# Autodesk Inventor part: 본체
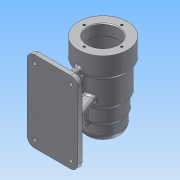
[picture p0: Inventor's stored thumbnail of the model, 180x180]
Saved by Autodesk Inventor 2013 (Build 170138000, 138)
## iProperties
Created: 2016-06
Part Number: 본체
Material: 알루미늄 6061
Document SubType Name: Modeling
Designer: Administrator
Density: 2.71 g/cm^3
Mass: 672.779 g
Surface Area: 647.12 cm^2
Volume: 248.258 cm^3
Author: Administrator
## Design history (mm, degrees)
sketch "스케치1"
  geometry: C1 r 34 at (0, 0); 1 further point
  constraints: 1 centre point, 1 coincident
  dimensions: "d0" = 68 diameter of C1
extrude "돌출1" new body sketch "스케치1" distance "d1" = 28; taper "d2" = 0 deg
sketch "스케치2"
  geometry: C1 r 34 at (0, 0) reference; C2 r 30 at (0, 0)
  constraints: 1 centre point, 1 coincident
  dimensions: "d3" = 60 diameter of C2
extrude "돌출2" join sketch "스케치2" distance "d4" = 39; taper "d5" = 0 deg
sketch "스케치3"
  geometry: C1 r 30 at (0, 0) reference; C2 r 27 at (0, 0)
  constraints: 1 centre point, 1 coincident
  dimensions: "d6" = 54 diameter of C2
extrude "돌출3" join sketch "스케치3" distance "d7" = 20; taper "d8" = 0 deg
sketch "스케치4"
  geometry: C1 r 27 at (0, 0) reference; C2 r 25 at (0, 0)
  constraints: 1 centre point, 1 coincident
  dimensions: "d9" = 50 diameter of C2
extrude "돌출4" join sketch "스케치4" distance "d10" = 25; taper "d11" = 0 deg
hole "구멍1" diameter "d14" = 42; stored, may be unused: countersink angle "d18" = 90 deg, drill point angle "d20" = 0 deg; dims "d12" = 10, "d13" = 10, "d15" = 6, "d16" = 4, "d17" = 2, "d19" = 15
hole "구멍2" diameter "d23" = 48; stored, may be unused: countersink angle "d27" = 90 deg, drill point angle "d29" = 0 deg; dims "d21" = 10, "d22" = 10, "d24" = 6, "d25" = 4, "d26" = 2, "d28" = 54
hole "구멍3" diameter "d32" = 42; stored, may be unused: countersink angle "d36" = 90 deg, drill point angle "d38" = 0 deg; dims "d30" = 10, "d31" = 10, "d33" = 6, "d34" = 4, "d35" = 2, "d37" = 12
hole "구멍4" diameter "d41" = 35; stored, may be unused: countersink angle "d45" = 90 deg, drill point angle "d47" = 0 deg; dims "d39" = 10, "d40" = 10, "d42" = 6, "d43" = 4, "d44" = 2, "d46" = 18
hole "구멍5" diameter "d50" = 32; stored, may be unused: countersink angle "d54" = 90 deg, drill point angle "d56" = 0 deg; dims "d48" = 10, "d49" = 10, "d51" = 6, "d52" = 4, "d53" = 2, "d55" = 4
hole "구멍6" diameter "d59" = 21; stored, may be unused: countersink angle "d63" = 90 deg, drill point angle "d65" = 0 deg; dims "d57" = 10, "d58" = 10, "d60" = 6, "d61" = 4, "d62" = 2, "d64" = 3
node "작업 평면1"
sketch "스케치5"
  geometry: L1 (-25, -112)-(25, -112) reference; L2 (-34, 0)-(34, 0) reference; L3 (27.711, -56)-(106.129, -56); L4 (-35, -112)-(35, -112); L5 (35, -112)-(35, 0); L6 (35, 0)-(-35, 0); L7 (-35, 0)-(-35, -112); L8 (-35, -112)-(35, 0); L9 (35, -112)-(-35, 0); 5 further points
  constraints: 14 end point, 5 midpoint, 2 parallel, 1 horizontal, 1 perpendicular, 1 point on line, 1 vertical alignment
  dimensions: "d69" = 56 distance between parallel lines of L3 L1; "d70" = 70 distance of L6.end L5.end; "d72" = 112 distance between parallel lines of L6 L4
extrude "돌출5" join sketch "스케치5" distance "d73" = 10; taper "d74" = 0 deg
fillet "모깎기7" dims "d133" = 3
sketch "스케치6"
  geometry: L1 (-35, 0)-(35, 0) reference; L2 (35, 0)-(35, 112) reference; L3 (4, 20)-(4, 92); L4 (4, 92)-(-4, 92); L5 (-4, 92)-(-4, 20); L6 (-4, 20)-(4, 20); L7 (4, 56)-(-4, 56); L8 (0, 92)-(0, 20); 1 further point
  constraints: 12 end point, 4 midpoint, 2 parallel, 1 perpendicular
  dimensions: "d75" = 8 distance between parallel lines of L5 L3; "d77" = 56 distance between parallel lines of L1 L7; "d79" = 20 distance between parallel lines of L1 L6; "d80" = 35 distance between parallel lines of L2 L8
extrude "돌출6" join sketch "스케치6" stored distance "d81" = 10; taper "d82" = 0 deg
node "작업 평면2"
sketch "스케치7"
  geometry: L1 (-70, 0)-(-70, 10) reference; L2 (-70, 10)-(-39, 10) reference; L3 (-39, 10)-(-39, 40.268) reference; L4 (-31, 40.268)-(-31, 10) reference; L5 (-31, 10)-(0, 10) reference; L6 (0, 10)-(0, 0) reference; L7 (0, 0)-(-70, 0) reference; L8 (-50.509, 44.32)-(-63, 10); L9 (-19.491, 44.32)-(-7, 10); C1 r 24 at (-35, 70) reference; A1 r 30 centre (-35, 70) between (-31, 40.268) and (-39, 40.268) reference; 1 further point
  constraints: 4 end point, 2 point on circle, 2 point on line
  dimensions: "d83" = 110 deg angle of L5 L9; "d84" = 110 deg angle of L2 L8 (= d83); "d85" = 7 distance from line of L8.end L1; "d86" = 7 distance from line of L9.end L6
  node "절단 모서리 투영1"
feature "리브1" dims "d87" = 1, "d88" = 8, "d89" = 0, "d90" = 0, "d91" = 1, "d92" = 1
feature "리브2" dims "d93" = 1, "d94" = 8, "d95" = 0, "d96" = 0, "d97" = 1, "d98" = 1
node "작업 평면3"
sketch "스케치8"
  geometry: L1 (60, -84)-(60, 28) reference; L2 (60, 28)-(70, 28) reference; L3 (70, 28)-(70, -84) reference; L4 (70, -84)-(60, -84) reference; L5 (16, 28)-(16, 2.657) reference; L6 (-16, 28)-(16, 28) reference; L7 (-16, 2.657)-(-16, 28) reference; L8 (0, -3)-(0, -36) reference; 5 further points
  constraints: 1 midpoint, 1 vertical alignment, 5 other
  dimensions: "d99" = 48 distance from line of L6 point (0, -20)
feature "엠보싱1" sketch "스케치8" dims "d100" = 0.5, "d101" = 0
fillet "모깎기1" dims "d102" = 10, "d114" = 0.3
sketch "스케치9"
  geometry: C1 r 21 at (0, 0) reference; 1 further point
  constraints: 1 vertical alignment
  dimensions: "d103" = 26 distance of C1.centre point (0, 26)
hole "구멍7" sketch "스케치9" at (0, 26) diameter "d104" = 3.242; stored, may be unused: countersink angle "d108" = 90 deg, drill point angle "d110" = 118 deg; dims "d105" = 8, "d106" = 4, "d107" = 2, "d109" = 11
sketch "스케치10"
  geometry: A1 r 10 centre (25, 102) between (35, 102) and (25, 112) reference; A2 r 10 centre (-25, 102) between (-25, 112) and (-35, 102) reference; A3 r 10 centre (-25, 10) between (-35, 10) and (-25, 0) reference; A4 r 10 centre (25, 10) between (25, 0) and (35, 10) reference; 5 further points
  constraints: 4 coincident
hole "구멍8" sketch "스케치10" at (25, 102), (25, 10), (-25, 10), (-25, 102) diameter "d115" = 5; stored, may be unused: countersink angle "d119" = 90 deg, drill point angle "d121" = 0 deg; dims "d116" = 8, "d117" = 9, "d118" = 4, "d120" = 11
fillet "모깎기2" dims "d122" = 3
chamfer "모따기1" distance "d123" = 1; stored, may be unused: second distance "d124" = 2, angle "d125" = 45 deg
chamfer "모따기2" distance "d126" = 4; stored, may be unused: second distance "d127" = 2, angle "d128" = 45 deg
fillet "모깎기8" dims "d134" = 3
node "솔리드1"
pattern_circular "원형 패턴1" dims angle "d112" = 360 deg
node "절단 모서리 투영2"
